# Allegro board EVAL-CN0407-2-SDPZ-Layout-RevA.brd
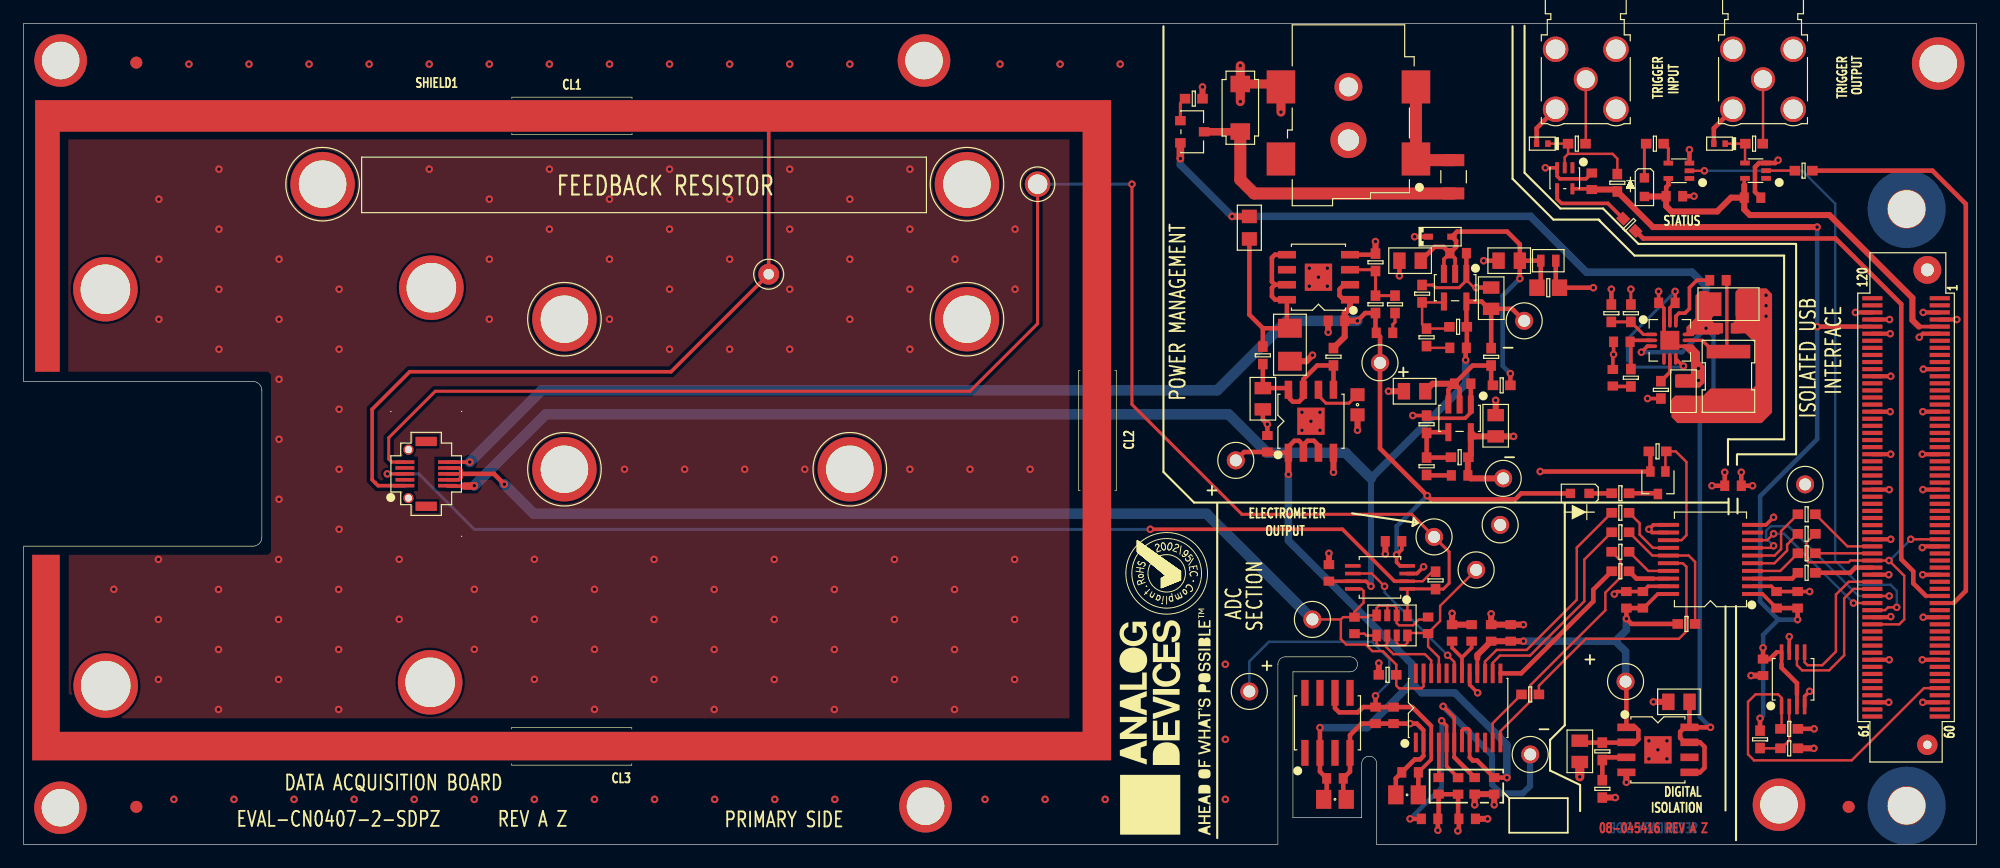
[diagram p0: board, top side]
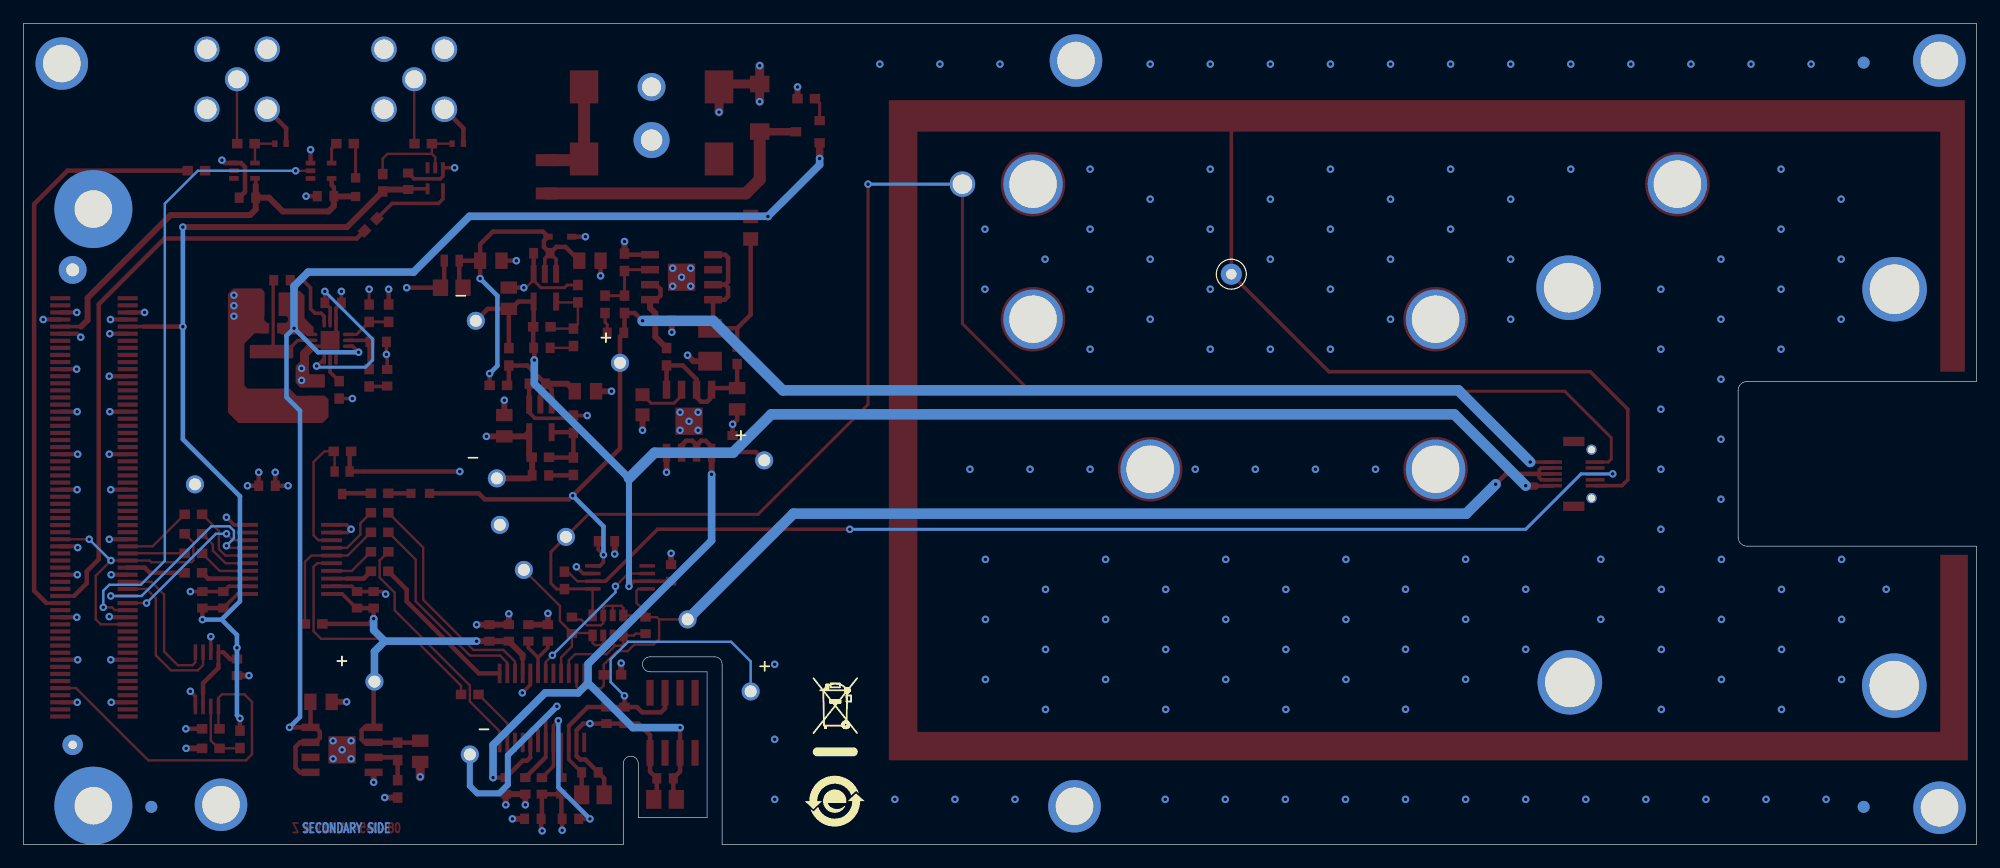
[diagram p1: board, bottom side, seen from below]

Outline 165.1 x 69.47 mm; copper layers: TOP, L2_GND, L3_POWER, BOTTOM. Coordinates in mm from the lower left corner of the outline.
Outline path: 0,39.18 19.38,39.18 arc(19.92,38.96) 20.14,38.42 20.14,26 arc(19.92,25.46) 19.38,25.24 0,25.24 0,0 106.05,0 106.05,15.24 arc(106.23,15.69) 106.68,15.88 112.14,15.88 arc(112.78,15.24) 112.14,14.6 107.32,14.6 107.32,2.26 113.13,2.26 113.14,6.83 arc(113.77,7.46) 114.41,6.83 114.41,0 165.1,0 165.1,69.47 0,69.47 0,39.18

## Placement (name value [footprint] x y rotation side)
AIN0  RED  [CNKEY5001TP]  122.81 23.23 0 top
C1  4.7uF  [C0805#2]  131.58 7.87 90 top
C2  4.7uF  [C0805#2]  139.96 12.06 0 top
C3  10uF  [C1206]  107.06 42.29 90 top
C4  4.7uF  [C0805#2]  104.78 37.72 90 top
C5  10uF  [C0603]  105.16 33.91 270 top
C6  10uF  [C0603]  111 44.31 0 top
C7  10000pF  [C0603]  121.29 42.03 0 top
C8  10uF  [C0603#2]  112.78 37.21 90 top
C9  10000pF  [C0603]  112.52 18.53 270 top
C10  10000pF  [C0603]  115.06 43.3 180 top
C11  0.1uF  [C0603]  121.29 50.04 180 top
C12  0.1uF  [C0603]  121.67 38.99 180 top
C13  4.7uF  [C0805#2]  124.08 46.23 270 top
C14  4.7uF  [C0805#2]  124.46 35.43 270 top
C15  10000pF  [C0603]  121.41 31.23 0 top
C16  4.7uF  [C0805#2]  117.22 49.4 0 top
C17  4.7uF  [C0805#2]  117.61 38.35 0 top
C18  10uF  [C0603]  144.53 30.35 180 top
C23  0.1uF  [C0603]  146.18 54.74 180 top
C24  0.1uF  [C0603]  147.07 14.99 90 top
C25  0.1uF  [C0603]  139.58 54.86 180 top
C26  0.1uF  [C0603]  132.59 56.12 270 top
C27  4.7uF  [C0805#2]  125.61 49.4 0 top
C28  0.1uF  [C0603]  119.64 4.95 90 top
C29  0.1uF  [C0603]  121.29 4.94 90 top
C30  1UF  [C0603]  118.88 2.16 180 top
C31  4.7uF  [C0805]  110.87 3.81 180 top
C32  0.1uF  [C0603]  110.87 5.59 180 top
C33  0.1uF  [C0603]  114.3 10.92 270 top
C34  1UF  [C0603]  115.83 10.92 270 top
C35  4.7uF  [C0805]  116.97 4.19 180 top
C36  0.1uF  [C0603]  117.22 6.1 180 top
C37  0.1uF  [C0603]  124.08 17.9 270 top
C38  1UF  [C0603]  125.73 17.9 270 top
C39  0.1uF  [C0603]  124.34 4.95 90 top
C40  0.1uF  [C0603]  122.43 17.9 270 top
C41  1UF  [C0603]  120.78 17.9 270 top
C42  0.1uF  [C0603]  122.69 4.95 90 top
C43  1UF  [C0603]  122.05 2.16 180 top
C44  0.1uF  [C0603]  149.99 20.7 270 top
C45  0.1uF  [C0603]  115.83 25.65 180 top
C46  0.1uF  [C0603]  110.36 22.98 90 top
C47  10000pF  [C0603]  118.75 18.54 270 top
C48  0.01uF  [C0603]  148.21 20.7 270 top
C49  0.1uF  [C0603]  135.51 20.7 270 top
C50  0.01uF  [C0603]  136.91 20.7 270 top
C51  10pF  [C0603]  135.13 42.54 0 top
C52  4.7uF  [C0805#2]  140.34 38.35 270 top
C53  10uF  [C1206]  144.15 45.72 180 top
C54  1UF  [C0603]  138.94 45.84 0 top
C55  2700PF  [C0603]  134.37 39.5 270 top
C56  1UF  [C0603]  144.02 43.69 180 top
C57  0.01uF  [C0603]  143.26 47.75 180 top
D1  SMAJ15CA-TR  [DO214AC_C]  102.87 62.35 270 top
D2  ESD9M5.0ST5G  [SOD923]  143.39 59.31 180 top
D3  ESD9M5.0ST5G  [SOD923]  128.4 59.31 180 top
D4  RB520S30  [SOD523F]  119.76 51.44 0 top
DS1  LG L29K-G2J1-24-Z  [LED0603-2]  131.57 29.71 180 top
DS2  LG L29K-G2J1-24-Z  [LED0603-2]  137.04 55.63 270 top
E1  600OHM AT 100MEGHZ  [L0805]  103.64 52.2 270 top
F1  0.1A  [F1206H30]  120.9 56.51 270 top
GND_BLK  BLK  [CNKEY5001TP]  124.84 27.04 0 top
GND_BLK2  BLK  [CNKEY5001TP]  150.62 30.47 0 top
J1  PJ-002AH-SMT  [CNCUI-PJ-002A_A]  112.01 61.71 180 top
J2  CONSMA002  [CNSMARAL598W276H401]  147.07 64.76 90 top
J3  CONSMA002  [CNSMARAL598W276H401]  132.08 64.76 90 top
J4  0682-0-15-15-32-27-10-0  [CNTPLD54]  85.73 55.88 0 top
L4  8.2 UH  [LSML193W134H67]  144.15 39.61 270 top
L5  560nH  [L7144]  128.91 49.4 180 top
NOREF  -  [unnamed]  3.11 3.1 0 top
NOREF#2  -  [#2]  58.55 215.51 0 top
NOREF#3  -  [#2]  3.11 3.1 0 top
NOREF#4  -  [#2]  340.95 180.36 0 top
NOREF#5  -  [#2]  107.32 2.26 0 top
NOREF#6  -  [#2]  106.05 0 0 top
NOREF#7  -  [unnamed]  76.25 3.23 0 top
NOREF#8  -  [#2]  165.1 0 0 top
NOREF#9  -  [unnamed]  6.94 13.44 0 top
NOREF#10  -  [#2]  51.69 6.07 0 top
NOREF#11  -  [#2]  -60.07 -138.08 0 top
NOREF#12  -  [unnamed]  79.76 44.45 0 top
NOREF#13  -  [#2]  0 69.47 0 top
NOREF#14  -  [#2]  114.41 0 0 top
NOREF#15  -  [#2]  44.75 4.93 0 top
NOREF#16  -  [#2]  345.19 168.28 0 top
NOREF#17  -  [unnamed]  34.37 13.72 0 top
NOREF#18  -  [#2]  352.68 6.07 0 top
NOREF#19  -  [unnamed]  79.76 55.88 0 top
NOREF#20  -  [#2]  77.85 136.13 0 top
NOREF#21  -  [#2]  3.11 3.1 0 top
NOREF#22  -  [#2]  107.32 14.6 0 top
NOREF#23  -  [#2]  8.51 10.51 0 top
NOREF#24  -  [#2]  100.03 6.05 90 top
NOREF#25  -  [#2]  0 69.47 0 top
NOREF#26  -  [unnamed]  161.88 66.09 0 top
NOREF#27  -  [unnamed]  34.47 47.12 0 top
NOREF#28  -  [#2]  -119.25 215.51 270 top
NOREF#29  -  [#2]  107.32 2.26 0 top
NOREF#30  -  [#2]  213.53 179.06 0 top
NOREF#31  -  [unnamed]  45.72 31.75 0 top
NOREF#32  -  [#2]  343.28 156.9 0 top
NOREF#33  -  [unnamed]  6.91 46.99 0 top
NOREF#34  -  [#2]  0 25.24 0 top
NOREF#35  -  [#2]  -341.5 -235.34 0 top
NOREF#36  -  [#2]  185.55 -89.29 90 top
NOREF#37  -  [#2]  0 0 0 top
NOREF#38  -  [#2]  349.43 180.36 0 top
NOREF#39  -  [#2]  0 0 0 top
NOREF#40  -  [unnamed]  148.42 3.35 0 top
NOREF#41  -  [#2]  -60.07 -138.08 0 top
NOREF#42  -  [#2]  347.09 156.85 0 top
NOREF#43  -  [unnamed]  9.53 3.17 0 top
NOREF#44  -  [#2]  268.1 82.79 0 top
NOREF#45  -  [#2]  185.55 215.51 180 top
NOREF#46  -  [unnamed]  3.13 66.35 0 top
NOREF#47  -  [unnamed]  9.53 66.17 0 top
NOREF#48  -  [#2]  339.52 163.12 0 top
NOREF#49  -  [#2]  104.99 1.24 0 top
NOREF#50  -  [unnamed]  25.28 55.88 0 top
NOREF#51  -  [unnamed]  154.31 3.17 0 top
NOREF#52  -  [#2]  113.14 2.26 0 top
NOREF#53  -  [#2]  20.04 38.8 0 top
NOREF#54  -  [unnamed]  45.72 44.45 0 top
NOREF#55  -  [#2]  -119.25 -89.29 0 top
NOREF#56  -  [#2]  0 39.18 0 top
NOREF#57  -  [#2]  165.1 0 90 top
NOREF#58  -  [unnamed]  69.85 31.75 0 top
NOREF#59  -  [#2]  338.87 171.37 0 top
NOREF#60  -  [unnamed]  76.13 66.34 0 top
NOREF#61  -  [unnamed]  154.31 3.17 180 bottom
NOREF#62  -  [unnamed]  9.53 66.17 180 bottom
NOREF#63  -  [#2]  96.53 3.66 180 bottom
NOREF#64  -  [unnamed]  9.53 3.17 180 bottom
NOREF#65  -  [#2]  96.68 7.52 180 bottom
P6  DF12(3.0)-10DP-0.5V  [CNHRS-DF12_3-10DP-05V]  34.04 31.36 90 top
P7  FX8-120S-SV(21)  [CNHRSFX8-120S-SV_A]  159.16 28.52 270 top
Q1  IRLML5203TRPBF  [SOT23-M3]  98.81 60.32 270 top
Q2  2N7002WT1G  [SOT323]  138.18 30.61 180 top
R1  100K  [R0603]  114.3 45.71 270 top
R2  1K  [R0603]  98.94 63.12 180 top
R3  10K  [R0603]  115.95 45.71 270 top
R4  100K  [R0603]  114.3 49.27 270 top
R5  1K  [R0603]  135 29.72 180 top
R6  100K  [R0603]  121.29 43.81 0 top
R7  10K  [R0603]  135.89 44.96 270 top
R8  100K  [R0603]  121.42 32.77 0 top
R9  32.4K  [R0603]  118.62 42.92 270 top
R10  49.9  [R0603]  135.76 52.44 315 top
R11  91K  [R0603]  118.62 32 270 top
R12  32.4K  [R0603]  118.24 46.61 270 top
R13  91K  [R0603]  118.62 35.56 270 top
R14  0  [R0603]  146.82 8.89 90 top
R15  100K  [R0603]  149.28 9.78 180 top
R16  100K  [R0603]  149.28 8.13 180 top
R17  49.9  [R0603]  146.31 59.31 180 top
R18  1K  [R0603]  137.93 59.31 0 top
R19  49.9  [R0603]  131.32 59.31 180 top
R20  10K  [R0603]  140.59 18.66 180 top
R22  49.9  [R0603]  135 26.42 180 top
R23  49.9  [R0603]  135 23.11 180 top
R24  49.9  [R0603]  135 24.77 180 top
R25  49.9  [R0603]  127.38 12.69 0 top
R26  49.9  [R0603]  135 28.07 0 top
R27  0  [R0603]  110.75 41.28 270 top
R28  0  [R0603]  104.78 41.39 270 top
R29  0  [R0603]  115.32 14.35 0 top
R30  0  [R0603]  124.97 38.85 180 top
R31  0  [R0603]  124.08 41.27 270 top
R32  32.4K  [R0603]  138.15 33.26 0 top
R33  49.9  [R0603]  150.5 57.02 0 top
R34  100K  [R0603]  133.48 4.7 90 top
R35  100K  [R0603]  134.75 56 270 top
R36  0  [R0603]  119.38 22.34 270 top
R37  32.4K  [R0603]  133.48 7.87 90 top
R38  49.9  [R0603]  150.75 27.94 180 top
R39  49.9  [R0603]  150.75 26.29 180 top
R40  49.9  [R0603]  150.75 24.64 180 top
R41  49.9  [R0603]  150.75 22.99 180 top
R43  32.4K  [R0603]  135.89 39.5 90 top
R44  88.7K  [R0603]  138.43 38.47 90 top
R45  86.6K  [R0603]  134.24 44.96 90 top
R46  2.2  [R0805]  128.91 47.12 180 top
REF+  RED  [CNKEY5001TP]  103.63 12.94 0 top
REF-  RED  [CNKEY5001TP]  127.38 7.61 0 top
RN1  10K  [R1206-8P]  115.7 18.53 180 top
SGND  BLK  [CNKEY5001TP]  108.97 19.04 0 top
U1  ADP7118ARDZ-2.5  [SO8NB-PAD2_3X2_3]  138.18 8 270 top
U2  ADP7118ARDZ-2.5  [SO8NB-PAD2_3X2_3]  109.48 48.01 90 top
U3  ADP7118ARDZ-2.5  [SO8NB-PAD2_3X2_3]  108.84 35.81 0 top
U4  ADP7182AUJZ-R7  [TSOT-5]  121.03 47.12 180 top
U5  ADP7182AUJZ-R7  [TSOT-5]  121.41 36.06 180 top
U8  24LC32A-I/MS  [MSOP8]  149.61 13.97 0 top
U9  SN74AHCT1G04DCKR  [SC70-5]  146.43 57.02 90 top
U10  SN74AHCT1G04DCKR  [SC70-5]  139.95 57.01 90 top
U11  74LVC1G14GW,125  [SOT353]  130.3 56.38 180 top
U12  ADR4525BRZ  [SO8]  110.24 10.29 0 top
U13  AD7172-2BRUZ  [TSSOP24]  121.29 11.55 0 top
U14  ADG1419BRMZ  [MSOP8]  114.68 22.6 90 top
U15  ADUM3151BRSZ  [SSOP20-4]  142.62 24.12 90 top
U17  ADP2442ACPZ  [QFN12_3X3_PAD1_6X1_6]  139.19 42.66 270 top
UNK+2.5VA  RED  [CNKEY5001TP]  102.49 32.5 0 top
UNK+3.3VISO  RED  [CNKEY5001TP]  135.44 13.78 0 top
UNK+5VA  RED  [CNKEY5001TP]  114.68 40.76 0 top
UNK-2.5VA  RED  [CNKEY5001TP]  125.09 30.98 0 top
UNK-5VA  RED  [CNKEY5001TP]  126.87 44.31 0 top
VGUARD  TP_VIA_LARGE  [TPC70D35]  63 48.26 0 top
VOUT  RED  [CNKEY5001TP]  119.25 26.03 0 top

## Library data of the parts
AIN0 REF+ REF- UNK+2.5VA UNK+3.3VISO UNK+5VA UNK-2.5VA UNK-5VA VOUT = CNTP1P: Tolerance: N/A; User Part Number: UPN; alternate symbols: (); part number: CNTP1P_TH-RED,E016323,CNKEY5001TP; tolerance: N/A
C1 C2 C4 C13 C14 C16 C17 C27 C52 = CAP: Tolerance: 10; User Part Number: UPN; alternate symbols: C0805H30; part number: CAP_SM-4.7UF,16V,10,E011042,C0805; tolerance: 10
C3 C53 = CAP: Tolerance: 10; User Part Number: UPN; alternate symbols: C1206H37; part number: CAP_SM-10UF,10V,10,E011047,C1206; tolerance: 10
C5 C6 C8 C18 = CAP: Tolerance: 20; User Part Number: UPN; alternate symbols: C0603L_ALT; part number: CAP_SM-10UF,6.3V,20,E007143,C0603; tolerance: 20
C7 C9 C10 C15 C47 = CAP: Tolerance: 10; User Part Number: UPN; alternate symbols: C0603L_ALT; part number: CAP_SM-10000PF,25V,10,E014286,C0603; tolerance: 10
C11 C12 C23-C26 C28 C29 C32 C33 C36 C37 C39 C40 C42 C44-C46 C49 = CAP: Tolerance: 10; User Part Number: UPN; alternate symbols: C0603L_ALT; part number: CAP_SM-0.1UF,25V,10,E013746,C0603; tolerance: 10
C30 C34 C38 C41 C43 C54 C56 = CAP: Tolerance: 10; User Part Number: UPN; alternate symbols: C0603L_ALT; part number: CAP_SM-1UF,25V,10,E025743,C0603; tolerance: 10
C31 C35 = CAP: Tolerance: 10; User Part Number: UPN; alternate symbols: (); part number: CAP_SM-4.7UF,16V,10,E011042,C0805; tolerance: 10
C48 C50 C57 = CAP: Tolerance: 10; User Part Number: UPN; alternate symbols: C0603L_ALT; part number: CAP_SM-0.01UF,50V,10,E017640,C0603; tolerance: 10
C51 = CAP: Tolerance: 5; User Part Number: UPN; alternate symbols: C0603L_ALT; part number: CAP_SM-10PF,50V,5,E010138,C0603; tolerance: 5
C55 = CAP: Tolerance: 5; User Part Number: UPN; alternate symbols: C0603L_ALT; part number: CAP_SM-2700PF,50V,5,E026401,C0603; tolerance: 5
D1 = DIO_V3: User Part Number: UPN; Tolerance: N/A; alternate symbols: (); part number: DIO_V3_SM-SMAJ15CA-TR,15V,N/A,E027980,DO214AC_C; tolerance: N/A
D2 D3 = DIOZNR: User Part Number: UPN; Tolerance: N/A; alternate symbols: (); part number: DIOZNR_SM-ESD9M5.0ST5G,5V,N/A,E027990,SOD923; tolerance: N/A
D4 = DIOSCHOTTKY: Tolerance: N/A; User Part Number: UPN; alternate symbols: (); part number: DIOSCHOTTKY_SM-RB520S30,30V,N/A,E012252,SOD523F; tolerance: N/A
DS1 DS2 = DIOLED: Tolerance: N/A; User Part Number: UPN; alternate symbols: (); part number: DIOLED_SM-LG L29K-G2J1-24-Z,N/A,N/A,E010948,LED0603-2; tolerance: N/A
E1 = FERRITE: Tolerance: 25; User Part Number: UPN; alternate symbols: (); part number: FERRITE_SM-600OHM AT 100MEGHZ,25,E020490,L0805; tolerance: 25
F1 = FSFUSE: Tolerance: N/A; User Part Number: UPN; alternate symbols: (); part number: FSFUSE_SM-0.1A,60V,E027979,F1206H30; tolerance: N/A
GND_BLK GND_BLK2 SGND = CNTP1P: Tolerance: N/A; User Part Number: UPN; alternate symbols: (); part number: CNTP1P_TH-BLK,E005347,CNKEY5001TP; tolerance: N/A
J1 = CN4P_V6: User Part Number: UPN; Tolerance: N/A; alternate symbols: (); part number: CN4P_V6_SM-PJ-002AH-SMT,E022246,CNCUI-PJ-002A_A; tolerance: N/A
J2 J3 = CNBNC5P: User Part Number: UPN; Tolerance: N/A; alternate symbols: (); part number: CNBNC5P_TH-CONSMA002,E028005,CNSMARAL598W276H401; tolerance: N/A
J4 = CNTP1P: Tolerance: N/A; User Part Number: UPN; alternate symbols: (); part number: CNTP1P_TH-0682-0-15-15-32-27-10-0,E014020,CNTPLD54; tolerance: N/A
L4 = IND: User Part Number: UPN; Tolerance: 20; alternate symbols: (); part number: IND_SM-8.2 UH,20,E027982,LSML193W134H67; tolerance: 20
L5 = IND: Tolerance: 20; User Part Number: UPN; alternate symbols: (); part number: IND_SM-560NH,20,E021672,L7144; tolerance: 20
P6 = CN10P_ODD_EVEN: User Part Number: UPN; Tolerance: N/A; alternate symbols: (); part number: CN10P_ODD_EVEN_SM-DF12(3.0)-10DP-0.5V,E017886,CNHRS-DF12_3-10DP-05V; tolerance: N/A
P7 = CN120P_V4: User Part Number: UPN; Tolerance: N/A; alternate symbols: (); part number: CN120P_V4_SM-FX8-120S-SV(21),E016993,CNHRSFX8-120S-SV_A; tolerance: N/A
Q1 = TRANPMOSFET_V12: User Part Number: UPN; Tolerance: N/A; alternate symbols: (); part number: TRANPMOSFET_V12_SM-IRLML5203TRPBF,E027978,SOT23-M3; tolerance: N/A
Q2 = TRANNMOSFET3P: User Part Number: UPN; Tolerance: N/A; alternate symbols: (); part number: TRANNMOSFET3P_SM-2N7002WT1G,E020753,SOT323; tolerance: N/A
R1 R4 R6 R8 R15 R16 R34 R35 = RES: Tolerance: 0.5; User Part Number: UPN; alternate symbols: R0603_A; part number: RES_SM-100K,E012705,1/10W,0.5,R0603; tolerance: 0.5
R2 R5 R18 = RES: Tolerance: 1; User Part Number: UPN; alternate symbols: R0603_A; part number: RES_SM-1K,E003678,1/10W,1,R0603; tolerance: 1
R3 R7 R20 = RES: Tolerance: 0.1; User Part Number: UPN; alternate symbols: R0603_A; part number: RES_SM-10K,E020748,1/10W,0.1,R0603; tolerance: 0.1
R9 R12 R32 R37 R43 = RES: Tolerance: 0.5; User Part Number: UPN; alternate symbols: R0603_A; part number: RES_SM-32.4K,E027989,1/10W,0.5,R0603; tolerance: 0.5
R10 R17 R19 R22-R26 R33 R38-R41 = RES: Tolerance: 1; User Part Number: UPN; alternate symbols: R0603_A; part number: RES_SM-49.9,E003673,1/10W,1,R0603; tolerance: 1
R11 R13 = RES: Tolerance: 1; User Part Number: UPN; alternate symbols: R0603_A; part number: RES_SM-91K,E022344,1/10W,1,R0603; tolerance: 1
R14 R27-R31 R36 = RES: Tolerance: 1; User Part Number: UPN; alternate symbols: R0603_A; part number: RES_SM-0,E004207,1/16W,1,R0603; tolerance: 1
R44 = RES: Tolerance: 1; User Part Number: UPN; alternate symbols: R0603_A; part number: RES_SM-88.7K,E027521,1/10W,1,R0603; tolerance: 1
R45 = RES: Tolerance: 1; User Part Number: UPN; alternate symbols: R0603_A; part number: RES_SM-86.6K,E027997,1/10W,1,R0603; tolerance: 1
R46 = RES: Tolerance: 1; User Part Number: UPN; alternate symbols: R0603_A; part number: RES_SM-2.2,E023444,1/3W,1,R0805; tolerance: 1
RN1 = RESNET_8P_4R: Tolerance: 0.1; User Part Number: UPN; alternate symbols: (); part number: RESNET_8P_4R_SM-10K,E027995,3/10W,0.1,R1206-8P; tolerance: 0.1
U1-U3 = ADP7118_V3: Tolerance: N/A; User Part Number: UPN; alternate symbols: (); part number: ADP7118_V3_SM-ADP7118ARDZ-2.5,E023599,SO8NB-PAD2_3X2_3; tolerance: N/A
U4 U5 = ADP7182: User Part Number: UPN; Tolerance: N/A; alternate symbols: (); part number: ADP7182_SM-ADP7182AUJZ-R7,E017566,TSOT-5; tolerance: N/A
U8 = IC24FC256: Tolerance: N/A; User Part Number: UPN; alternate symbols: (); part number: IC24FC256_SM-24LC32A-I/MS,E014160,MSOP8; tolerance: N/A
U9 U10 = 741G04: Tolerance: N/A; User Part Number: UPN; alternate symbols: (); part number: 741G04_SM-SN74AHCT1G04DCKR,E027985,SC70-5; tolerance: N/A
U11 = 741G14: User Part Number: UPN; Tolerance: N/A; alternate symbols: (); part number: 741G14_SM-74LVC1G14GW,125,E027983,SOT353; tolerance: N/A
U12 = ADR45XX: Tolerance: N/A; User Part Number: UPN; alternate symbols: (); part number: ADR45XX_SM-ADR4525BRZ,E016680,SO8; tolerance: N/A
U13 = AD7172_2: Tolerance: N/A; User Part Number: UPN; alternate symbols: (); part number: AD7172_2_SM-AD7172-2BRUZ,E026892,TSSOP24; tolerance: N/A
U14 = ADG1419: Tolerance: N/A; User Part Number: UPN; alternate symbols: (); part number: ADG1419_SM-ADG1419BRMZ,E014853,MSOP8; tolerance: N/A
U15 = ADUM3151: Tolerance: N/A; User Part Number: UPN; alternate symbols: (); part number: ADUM3151_SM-ADUM3151BRSZ,E021805,SSOP20-4; tolerance: N/A
U17 = ADP2442: User Part Number: UPN; Tolerance: N/A; alternate symbols: (); part number: ADP2442_SM-ADP2442ACPZ,E018413,QFN12_3X3_PAD1_6X1_6; tolerance: N/A
VGUARD = NCTESTPAD: Tolerance: N/A; User Part Number: UPN; alternate symbols: (); part number: NCTESTPAD_TH-TP_VIA_LARGE,E012150,TPC70D35; tolerance: N/A

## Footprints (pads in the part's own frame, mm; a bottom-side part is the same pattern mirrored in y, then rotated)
C0603
  rect 0.762x0.889 smd: 1(-0.699,0) 2(0.699,0)
C0603#2
  rect 1.092x1.194 smd: 1(-0.851,0) 2(0.851,0)
C0805
  rect 1.295x1.6 smd: 1(-0.953,0) 2(0.953,0)
C0805#2
  rect 1.041x1.397 smd: 1(-0.9,0) 2(0.9,0)
C1206
  rect 1.6x2.007 smd: 1(-1.397,0) 2(1.397,0)
CNCUI-PJ-002A_A
  round 3.048 hole 1.803 unplated: (0,2.1)
  round 2.362 hole 1.6 unplated: (0,-2.4)
  rect 2.413x2.794 smd: 1A(-5.707,3.7) 1B(-5.707,-2.4) 2(5.707,-2.4) 3(5.707,3.7)
CNHRS-DF12_3-10DP-05V
  rect 0.787x1.803 smd: (-2.744,0) (2.744,0)
  round 0.864 hole 0.61 unplated: (-2.05,1.5) (2.05,1.5)
  rect 0.305x1.6 smd: 1(-1,1.8) 2(-1,-1.8) 3(-0.5,1.8) 4(-0.5,-1.8) 5(0,1.8) 6(0,-1.8) 7(0.5,1.8) 8(0.5,-1.8) 9(1,1.8) 10(1,-1.8)
CNHRSFX8-120S-SV_A
  round 3.302 hole 3.175 unplated: (-25.25,0.05) (25.25,0.05)
  round 2.362 hole 1.092 unplated: (-20.1,1.8)
  round 1.727 hole 0.711 unplated: (20.1,1.8)
  rect 0.356x1.702 smd: 1(-17.7,2.851) 2(-17.1,2.851) 3(-16.5,2.851) 4(-15.9,2.851) 5(-15.3,2.851) 6(-14.7,2.851) 7(-14.1,2.851) 8(-13.5,2.851) 9(-12.9,2.851) 10(-12.3,2.851) 11(-11.7,2.851) 12(-11.1,2.851) 13(-10.5,2.851) 14(-9.9,2.851) 15(-9.3,2.851) 16(-8.7,2.851) 17(-8.1,2.851) 18(-7.5,2.851) 19(-6.9,2.851) 20(-6.3,2.851) 21(-5.7,2.851) 22(-5.1,2.851) 23(-4.5,2.851) 24(-3.9,2.851) 25(-3.3,2.851) 26(-2.7,2.851) 27(-2.1,2.851) 28(-1.5,2.851) 29(-0.9,2.851) 30(-0.3,2.851) 31(0.3,2.851) 32(0.9,2.851) 33(1.5,2.851) 34(2.1,2.851) 35(2.7,2.851) 36(3.3,2.851) 37(3.9,2.851) 38(4.5,2.851) 39(5.1,2.851) 40(5.7,2.851) 41(6.3,2.851) 42(6.9,2.851) 43(7.5,2.851) 44(8.1,2.851) 45(8.7,2.851) 46(9.3,2.851) 47(9.9,2.851) 48(10.5,2.851) 49(11.1,2.851) 50(11.7,2.851) 51(12.3,2.851) 52(12.9,2.851) 53(13.5,2.851) 54(14.1,2.851) 55(14.7,2.851) 56(15.3,2.851) 57(15.9,2.851) 58(16.5,2.851) 59(17.1,2.851) 60(17.7,2.851) 61(17.7,-2.851) 62(17.1,-2.851) 63(16.5,-2.851) 64(15.9,-2.851) 65(15.3,-2.851) 66(14.7,-2.851) 67(14.1,-2.851) 68(13.5,-2.851) 69(12.9,-2.851) 70(12.3,-2.851) 71(11.7,-2.851) 72(11.1,-2.851) 73(10.5,-2.851) 74(9.9,-2.851) 75(9.3,-2.851) 76(8.7,-2.851) 77(8.1,-2.851) 78(7.5,-2.851) 79(6.9,-2.851) 80(6.3,-2.851) 81(5.7,-2.851) 82(5.1,-2.851) 83(4.5,-2.851) 84(3.9,-2.851) 85(3.3,-2.851) 86(2.7,-2.851) 87(2.1,-2.851) 88(1.5,-2.851) 89(0.9,-2.851) 90(0.3,-2.851) 91(-0.3,-2.851) 92(-0.9,-2.851) 93(-1.5,-2.851) 94(-2.1,-2.851) 95(-2.7,-2.851) 96(-3.3,-2.851) 97(-3.9,-2.851) 98(-4.5,-2.851) 99(-5.1,-2.851) 100(-5.7,-2.851) 101(-6.3,-2.851) 102(-6.9,-2.851) 103(-7.5,-2.851) 104(-8.1,-2.851) 105(-8.7,-2.851) 106(-9.3,-2.851) 107(-9.9,-2.851) 108(-10.5,-2.851) 109(-11.1,-2.851) 110(-11.7,-2.851) 111(-12.3,-2.851) 112(-12.9,-2.851) 113(-13.5,-2.851) 114(-14.1,-2.851) 115(-14.7,-2.851) 116(-15.3,-2.851) 117(-15.9,-2.851) 118(-16.5,-2.851) 119(-17.1,-2.851) 120(-17.7,-2.851)
CNKEY5001TP
  round 1.524 hole 1.016: 1(0,0)
CNSMARAL598W276H401
  round 2.032 hole 1.524: 1(0,0)
  round 2.159 hole 1.651: 2(2.54,-2.553) 3(2.54,2.553) 4(-2.54,2.553) 5(-2.54,-2.553)
CNTPLD54
  round 2.159 hole 1.651: 1(0,0)
DO214AC_C
  rect 1.397x1.651 smd: 1(-2.014,0) 2(2.014,0)
F1206H30
  rect 1.016x1.803 smd: 1(-1.41,0) 2(1.41,0)
L0805
  rect 1.143x1.27 smd: 1(-0.953,0) 2(0.953,0)
L7144
  rect 0.635x1.016 smd: 1(-0.635,0) 2(0.635,0)
LED0603-2
  rect 0.787x0.787 smd: A(0.787,0) C(-0.787,0)
LSML193W134H67
  rect 1.143x3.683 smd: 1(-2.095,0) 2(2.095,0)
MSOP8
  rect 0.305x1.321 smd: 1(-0.975,-2.3) 2(-0.325,-2.3) 3(0.325,-2.3) 4(0.975,-2.3) 5(0.975,2.3) 6(0.325,2.3) 7(-0.325,2.3) 8(-0.975,2.3)
QFN12_3X3_PAD1_6X1_6
  oval 0.305x0.991 smd: 1(-0.5,-1.57) 2(0,-1.57) 3(0.5,-1.57) 7(0.5,1.57) 8(0,1.57) 9(-0.5,1.57)
  oval 0.991x0.305 smd: 4(1.57,-0.5) 5(1.57,0) 6(1.57,0.5) 10(-1.57,0.5) 11(-1.57,0) 12(-1.57,-0.5)
  rect 1.6x1.6 smd: PAD(0,0)
R0603
  rect 0.889x0.813 smd: 1(-0.737,0) 2(0.737,0)
R0805
  rect 1.295x1.397 smd: 1(-0.953,0) 2(0.953,0)
R1206-8P
  rect 0.711x0.991 smd: 1(-1.302,-0.85) 4(1.302,-0.85) 5(1.302,0.85) 8(-1.302,0.85)
  rect 0.508x0.991 smd: 2(-0.4,-0.85) 3(0.4,-0.85) 6(0.4,0.85) 7(-0.4,0.85)
SC70-5
  rect 0.406x0.813 smd: 1(-0.65,-0.89) 2(0,-0.89) 3(0.65,-0.89) 4(0.65,0.89) 5(-0.65,0.89)
SO8
  rect 0.61x2.184 smd: 1(-1.905,-2.54) 2(-0.635,-2.54) 3(0.635,-2.54) 4(1.905,-2.54) 5(1.905,2.54) 6(0.635,2.54) 7(-0.635,2.54) 8(-1.905,2.54)
SO8NB-PAD2_3X2_3
  rect 0.635x1.524 smd: 1(-1.905,-2.667) 2(-0.635,-2.667) 3(0.635,-2.667) 4(1.905,-2.667) 5(1.905,2.667) 6(0.635,2.667) 7(-0.635,2.667) 8(-1.905,2.667)
  rect 2.311x2.311 smd: PAD(0,0)
SOD523F
  rect 0.787x0.508 smd: A(1,0) C(-1,0)
SOD923
  rect 0.457x0.559 smd: A(0.479,0) C(-0.479,0)
SOT23-M3
  rect 0.787x0.889 smd: 1(-0.94,-1.003) 2(0.94,-1.003) 3(0,1.003)
SOT323
  rect 0.711x0.889 smd: 1(-0.635,-0.953) 2(0.635,-0.953) 3(0,0.953)
SOT353
  rect 0.33x0.94 smd: 1(-0.65,-0.89) 2(0,-0.89) 3(0.65,-0.89) 4(0.65,0.89) 5(-0.65,0.89)
SSOP20-4
  rect 0.33x1.778 smd: 1(-2.925,-3.555) 2(-2.275,-3.555) 3(-1.625,-3.555) 4(-0.975,-3.555) 5(-0.325,-3.555) 6(0.325,-3.555) 7(0.975,-3.555) 8(1.625,-3.555) 9(2.275,-3.555) 10(2.925,-3.555) 11(2.925,3.555) 12(2.275,3.555) 13(1.625,3.555) 14(0.975,3.555) 15(0.325,3.555) 16(-0.325,3.555) 17(-0.975,3.555) 18(-1.625,3.555) 19(-2.275,3.555) 20(-2.925,3.555)
TPC70D35
  round 1.778 hole 0.889: 1(0,0)
TSOT-5
  rect 0.508x1.524 smd: 1(-0.95,-1.17) 2(0,-1.17) 3(0.95,-1.17) 4(0.95,1.17) 5(-0.95,1.17)
TSSOP24
  rect 0.33x1.651 smd: 1(-3.575,-2.92) 2(-2.925,-2.92) 3(-2.275,-2.92) 4(-1.625,-2.92) 5(-0.975,-2.92) 6(-0.325,-2.92) 7(0.325,-2.92) 8(0.975,-2.925) 9(1.625,-2.925) 10(2.275,-2.925) 11(2.925,-2.925) 12(3.575,-2.925) 13(3.575,2.925) 14(2.925,2.925) 15(2.275,2.925) 16(1.625,2.93) 17(0.975,2.93) 18(0.325,2.93) 19(-0.325,2.93) 20(-0.975,2.93) 21(-1.625,2.93) 22(-2.275,2.93) 23(-2.925,2.93) 24(-3.575,2.93)
unnamed
  round 4.445 hole 3.175 unplated: (0,0)

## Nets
+2.5VA: C5.2(N2) C31.2(N2) C32.2(N2) C39.2(N2) U3.1(VOUT1) U3.2(VOUT2) U3.3(SENSE/ADJ) U12.2(VIN) U13.7(AVDD1) U13.8(AVDD2) UNK+2.5VA.1
+3.3VIO: C24.2(N2) C26.2(N2) C44.2(N2) C48.2(N2) P7.116(VIO(+3.3V)) R14.2(N2) R35.2(N2) U8.3(A2) U8.8(VCC) U11.5(VCC) U15.1(VDD1)
+3.3VISO: C1.2(N2) C37.2(N2) C38.2(N2) C49.2(N2) C50.2(N2) R20.2(N2) R37.2(N2) U1.1(VOUT1) U1.2(VOUT2) U13.16(IOVDD) U15.20(VDD2) UNK+3.3VISO.1
+5V_USB: C23.2(N2) C25.2(N2) DS2.A(P) P7.5(USB_VBUS) U9.5(VCC) U10.5(VCC)
+5VA: C6.2(N2) C10.2(N2) C45.1(N1) DS1.A(P) P6.10(N5) R1.2(N2) R27.1(N1) U2.1(VOUT1) U2.2(VOUT2) U14.4(VDD) UNK+5VA.1
+VIN_PROTECTED: C2.2(N2) C53.2(N2) C56.2(N2) E1.1(N1) Q1.2(S) U1.5(EN) U1.7(VIN1) U1.8(VIN2) U17.3(EN) U17.9(VIN)
-2.5VA: C14.2(N2) C15.2(N2) C28.1(N1) C29.1(N1) C30.1(N1) C31.1(N1) C32.1(N1) C33.2(N2) C34.2(N2) C35.2(N2) C36.2(N2) C42.2(N2) C43.2(N2) R8.2(N2) REF-.1(N1) U5.5(VOUT) U12.4(GND) U13.2(REF-) U13.6(AVSS) U14.3(GND) UNK-2.5VA.1
-5.8V_RAW: C51.1(N1) C52.1(N1) C54.1(N1) C55.1(N1) L5.1(N1) R7.1(N1) R44.1(N1) R46.1(N1) U17.7(PGND) U17.12(AGND) U17.PAD
-5VA: C7.2(N2) C13.2(N2) C46.1(N1) P6.2(N1) R6.2(N2) R31.1(N1) U4.5(VOUT) U14.7(VSS) UNK-5VA.1
AGND: C1.1(N1) C2.1(N1) C3.1(N1) C4.1(N1) C5.1(N1) C6.1(N1) C8.1(N1) C11.1(N1) C12.1(N1) C13.1(N1) C14.1(N1) C16.1(N1) C17.1(N1) C18.2(N2) C27.1(N1) C37.1(N1) C38.1(N1) C39.1(N1) C40.1(N1) C41.1(N1) C42.1(N1) C43.1(N1) C45.2(N2) C46.2(N2) C49.1(N1) C50.1(N1) C52.2(N2) C53.1(N1) C56.1(N1) D1.1(N1) D4.C(N) GND_BLK.1(N1) J1.2(N3) L4.2(N2) Q2.2(S) R2.1(N1) R4.1(N1) R12.1(N1) R13.1(N1) R29.1(N1) R32.1(N1) R34.1(N1) R45.2(N2) U1.4(GND) U1.PAD U2.4(GND) U2.PAD U3.4(GND) U3.PAD U4.1(GND) U5.1(GND) U13.17(DGND) U15.11(GND2_1) U15.12(VIC) U15.19(GND2_2)
AGND2: C18.1(N1) C23.1(N1) C24.1(N1) C25.1(N1) C26.1(N1) C44.1(N1) C48.1(N1) D2.A(P) D3.A(P) GND_BLK2.1(N1) J2.2(SH1) J2.3(SH2) J2.4(SH3) J2.5(SH4) J3.2(SH1) J3.3(SH2) J3.4(SH3) J3.5(SH4) P7.3(GND1) P7.4(GND2) P7.6(GND3) P7.11(GND4) P7.17(GND5) P7.23(GND6) P7.28(GND7) P7.36(GND8) P7.40(GND9) P7.46(GND10) P7.52(GND11) P7.58(GND12) P7.63(GND13) P7.69(GND14) P7.75(GND15) P7.81(GND16) P7.86(GND17) P7.93(GND18) P7.98(GND19) P7.104(GND20) P7.109(GND21) P7.115(GND22) P7.117(GND23) P7.118(GND24) R15.1(N1) R16.1(N1) U8.4(VSS) U8.7(WP) U9.3(GND) U10.3(GND) U11.3(GND) U15.2(GND1_1) U15.10(GND1_2)
CS: R20.1(N1) R22.1(N1) U15.15(SSS_N)
DIN: R24.1(N1) U15.17(SI)
DOUT: R25.2(N2) U15.16(SO)
EN_ADCOFFSETCAL: U13.19(GPIO0) U14.6(IN)
GP_LED_ON: P7.76(GPIO5) U10.2(A)
LED_ONI: Q2.1(G) R32.2(N2) U15.13(VOB)
SCLK: R23.1(N1) U15.18(SCLK)
SPI_MISO_SDP: P7.35(SERIAL_INT) P7.74(GPIO7) P7.83(SPI_MISO) R39.1(N1)
START_TRIGGER_OUT: R33.1(N1) U9.2(A)
SYNCI: R26.2(N2) U15.14(VOA)
TRIGGER_INPUT: P7.43(GPIO0) R10.2(N2)
UNNAMED_3_ADP2442_I8_BST: C57.2(N2) U17.10(BST)
UNNAMED_3_ADP2442_I8_COMP: C51.2(N2) R43.2(N2) U17.2(COMP)
UNNAMED_3_ADP2442_I8_FB: R7.2(N2) R45.1(N1) U17.1(FB)
UNNAMED_3_ADP2442_I8_FREQ: R44.2(N2) U17.5(FREQ)
UNNAMED_3_ADP2442_I8_SW: C57.1(N1) L4.1(N1) U17.8(SW)
UNNAMED_3_ADP2442_I8_SYNC: C54.2(N2) U17.6(SYNC/MODE) U17.11(VCC)
UNNAMED_3_ADP7118V3_I3_EN: C4.2(N2) R27.2(N2) R28.2(N2) U3.5(EN) U3.7(VIN1) U3.8(VIN2)
UNNAMED_3_ADP7118V3_I3_SS: C8.2(N2) U3.6(SS)
UNNAMED_3_ADP7118V3_I4_EN: C3.2(N2) E1.2(N2) R28.1(N1) U2.5(EN) U2.7(VIN1) U2.8(VIN2)
UNNAMED_3_ADP7118V3_I4_SENSE: R1.1(N1) R3.1(N1) R4.2(N2) U2.3(SENSE/ADJ)
UNNAMED_3_ADP7118V3_I5_SENSE: R34.2(N2) R37.1(N1) U1.3(SENSE/ADJ)
UNNAMED_3_ADP7182_I6_ADJ: R6.1(N1) R9.1(N1) R12.2(N2) U4.4(ADJ)
UNNAMED_3_ADP7182_I6_EN: C11.2(N2) C16.2(N2) C27.2(N2) D4.A(P) L5.2(N2) R30.1(N1) R46.2(N2) U4.2(VIN) U4.3(EN)
UNNAMED_3_ADP7182_I7_ADJ: R8.1(N1) R11.1(N1) R13.2(N2) U5.4(ADJ)
UNNAMED_3_ADP7182_I7_EN: C12.2(N2) C17.2(N2) R30.2(N2) R31.2(N2) U5.2(VIN) U5.3(EN)
UNNAMED_3_CAP_I33_N1: C10.1(N1) R3.2(N2)
UNNAMED_3_CAP_I56_N1: C15.1(N1) R11.2(N2)
UNNAMED_3_CAP_I57_N1: C7.1(N1) R9.2(N2)
UNNAMED_3_CAP_I91_N2: C55.2(N2) R43.1(N1)
UNNAMED_3_CN4PV6_I1_N1: F1.1(N1) J1.1A(N1) J1.1B(N2)
UNNAMED_3_DIOLED_I44_N: DS1.C(N) R5.2(N2)
UNNAMED_3_DIOV3_I120_N2: D1.2(N2) F1.2(N2) Q1.3(D)
UNNAMED_3_RES_I16_N2: Q1.1(G) R2.2(N2)
UNNAMED_3_RES_I43_N1: Q2.3(D) R5.1(N1)
UNNAMED_4_AD71722_I1_AIN0: AIN0.1(N1) C47.2(N2) RN1.7(N2) RN1.8(N2) U13.21(AIN0)
UNNAMED_4_AD71722_I1_AIN1: C9.2(N2) RN1.5(N2) RN1.6(N2) U13.22(AIN1)
UNNAMED_4_AD71722_I1_AIN2: C9.1(N1) C47.1(N1) P6.4(N2) P6.6(N3) P6.8(N4) R29.2(N2) RN1.2(N1) RN1.3(N1) RN1.4(N1) SGND.1(N1) U13.23(AIN2) U14.8(SB)
UNNAMED_4_AD71722_I1_CSN: R22.2(N2) U13.14(CS_N)
UNNAMED_4_AD71722_I1_DIN: R24.2(N2) U13.12(DIN)
UNNAMED_4_AD71722_I1_DOUT: R25.1(N1) U13.11(DOUT/RDY_N)
UNNAMED_4_AD71722_I1_REF: C33.1(N1) C34.1(N1) C35.1(N1) C36.1(N1) REF+.1(N1) U12.6(VOUT) U13.3(REF+)
UNNAMED_4_AD71722_I1_REFOUT: C28.2(N2) U13.4(REFOUT)
UNNAMED_4_AD71722_I1_SCLK: R23.2(N2) U13.13(SCLK)
UNNAMED_4_AD71722_I1_SYNCN: R26.1(N1) U13.15(SYNC_N/ERROR_N)
UNNAMED_4_ADG1419_I8_D: J4.1(N1) P6.9(N5) R36.2(N2) RN1.1(N1) U14.1(D) VOUT.1(N1)
UNNAMED_4_ADG1419_I8_SA: P6.5(N3) R36.1(N1) U14.2(SA)
UNNAMED_4_CAP_I35_N2: C29.2(N2) C30.2(N2) U13.5(REGCAPA)
UNNAMED_4_CAP_I42_N2: C40.2(N2) C41.2(N2) U13.18(REGCAPD)
UNNAMED_5_741G04_I48_Y: D2.C(N) R17.2(N2) U9.4(Y)
UNNAMED_5_741G04_I49_Y: R18.2(N2) U10.4(Y)
UNNAMED_5_741G14_I52_Y: R10.1(N1) U11.4(Y)
UNNAMED_5_ADUM3151_I16_MCLK: R41.2(N2) U15.3(MCLK)
UNNAMED_5_ADUM3151_I16_MI: R39.2(N2) U15.5(MI)
UNNAMED_5_ADUM3151_I16_MO: R40.2(N2) U15.4(MO)
UNNAMED_5_ADUM3151_I16_MSSN: R38.2(N2) U15.6(MSS_N)
UNNAMED_5_ADUM3151_I16_VIA: P7.78(GPIO1) U15.7(VIA)
UNNAMED_5_ADUM3151_I16_VIB: P7.77(GPIO3) U15.8(VIB)
UNNAMED_5_CN120PV4_I1_EEPROMA0: P7.56(EEPROM_A0) R15.2(N2) U8.1(A0)
UNNAMED_5_CN120PV4_I1_GPIO2: P7.44(GPIO2) R33.2(N2)
UNNAMED_5_CN120PV4_I1_SCL0: P7.79(SCL_0) U8.6(SCL)
UNNAMED_5_CN120PV4_I1_SDA0: P7.80(SDA_0) U8.5(SDA)
UNNAMED_5_CN120PV4_I1_SPICLK: P7.82(SPI_CLK) R41.1(N1)
UNNAMED_5_CN120PV4_I1_SPIMOSI: P7.84(SPI_MOSI) R40.1(N1)
UNNAMED_5_CN120PV4_I1_SPISELA: P7.85(SPI_SEL_A) R38.1(N1)
UNNAMED_5_CNBNC5P_I53_CNTR: J2.1(CNTR) R17.1(N1)
UNNAMED_5_CNBNC5P_I54_CNTR: J3.1(CNTR) R19.1(N1)
UNNAMED_5_DIOLED_I62_N: DS2.C(N) R18.1(N1)
UNNAMED_5_IC24FC256_I3_A1: R14.1(N1) R16.2(N2) U8.2(A1)
UNNAMED_5_RES_I26_N1: D3.C(N) R19.2(N2) R35.1(N1) U11.2(A)
VGUARD: P6.1(N1) VGUARD.1(N1)

Pads without a net: J1 3; P6 3 7; P7 1 2 7 8 9 10 12 13 14 15 16 18 19 20 21 22 24 25 26 27 29 30 31 32 33 34 37 38 39 41 42 45 47 48 49 50 51 53 54 55 57 59 60 61 62 64 65 66 67 68 70 71 72 73 87 88 89 90 91 92 94 95 96 97 99 100 101 102 103 105 106 107 108 110 111 112 113 114 119 120; U1 6; U2 6; U9 1; U10 1; U11 1; U12 1 3 5 7 8; U13 1 9 10 20 24; U14 5; U15 9; U17 4

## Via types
v1: diameter 0.635, hole 0.305, TOP to BOTTOM, 279 vias

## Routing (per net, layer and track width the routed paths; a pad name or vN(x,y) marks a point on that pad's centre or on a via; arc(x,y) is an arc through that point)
+2.5VA: length 70.3
  TOP w0.305: U13.7 121.61,9.64 121.75,9.78 122.13,9.78 122.26,9.65 U13.8 122.26,7.36
  TOP w0.381: 122.26,7.36 122.54,7.09 122.9,7.09 C39.2 v1(125.42,5.65) ; UNK+2.5VA.1 103.2,33.21 C5.2 105.22,33.15 U3.1 106.94,33.66 107.45,34.16 107.83,34.16 108.21,33.78 ; v1(109.6,9.88) U12.2 109.6,6.16 C32.2 110.18,4.06 C31.2 ; 108.21,33.78 U3.2 ; 108.21,33.78 108.21,33.81 108.56,34.16 109.1,34.16 109.48,33.78 U3.3
  TOP w0.508: U3.1 v1(106.94,31.32)
  BOTTOM w0.635: v1(125.42,5.65) 125.42,8.42 121.01,12.83 118.22,12.83 117.38,13.66 ; 117.38,13.66 113.6,9.88 v1(109.6,9.88) ; 117.38,13.66 117.38,15.27 106.94,25.71 v1(106.94,31.32)
+3.3VIO: length 87.4
  TOP w0.305: U15.1 147.02,21.2 C48.2 ; 148.23,16.27 U8.8 148.63,15.24 ; 154.95,43.82 P7.116 ; U11.5 132.53,55.49 C26.2 ; U8.3 149.93,12.7
  TOP w0.381: v1(146.82,10.67) R14.2 ; 148.23,16.27 147.64,15.68 C24.2 v1(147.07,16.64) ; 148.63,15.24 148.63,14.94 149.93,13.64 149.93,12.7 ; 154.95,43.82 151.65,43.82 v1(151.64,43.82) ; v1(149.99,19.02) C44.2 C48.2
  TOP w0.508: v1(151.64,52.25) 137.76,52.25 R35.2 134.58,55.43 C26.2
  BOTTOM w0.381: v1(146.82,10.67) 147.07,10.92 v1(147.07,16.64) 147.07,17.73 148.37,19.02 ; 148.37,19.02 146.82,20.57 146.82,29.46 151.64,34.29 v1(151.64,43.82) v1(151.64,52.25) ; 148.37,19.02 v1(149.99,19.02)
+3.3VISO: length 40.2
  TOP w0.305: U15.20 138.17,21.2 136.97,20 C50.2 ; 122.91,15.75 U13.16
  TOP w0.381: R20.2 135.95,18.66 v1(135.51,19.1) C49.2 C50.2 ; C1.2 131.74,8.61 R37.2 135.49,8.61 U1.2 136.27,8.64 136.53,8.89 136.53,9.65 136.27,9.91 U1.1 135.51,13.71 UNK+3.3VISO.1
  TOP w0.508: v1(126.8,17.2) C38.2 C37.2 122.91,16.03 122.91,15.75
  BOTTOM w0.635: 134.57,17.2 v1(126.8,17.2) ; 134.57,17.2 135.44,16.33 UNK+3.3VISO.1 ; 134.57,17.2 135.51,18.14 v1(135.51,19.1)
+5V_USB: length 36
  TOP w0.305: U9.5 145.48,56.31 145.48,55.79 ; 160.25,43.82 P7.5
  TOP w0.381: U10.5 139.06,55.81 138.88,55.63 C25.2
  TOP w0.508: 160.25,43.82 159.7,44.37 159.7,46.25 152.69,53.26 145.96,53.26 145.48,53.74 C23.2 ; C23.2 145.48,55.79 ; C23.2 144.36,54.74 143.19,53.57 139.32,53.57 138.88,54.01 C25.2 138.85,54.84 DS2.A
+5VA: length 130.8
  TOP w0.305: C45.1 116.53,24.96 v1(116.08,24.51) 116.08,23.88 116.39,23.57 U14.4 ; P6.10 v1(37.72,32.36)
  TOP w0.381: U2.1 111.61,46.1 111.26,46.45 111.26,46.99 111.64,47.37 U2.2 ; DS1.A 126.62,29.71 126.11,29.2 118.99,29.2 v1(118.68,29.51) 114.68,33.51 UNK+5VA.1 114.68,40.76 114.68,42.98 C10.2 114.3,43.36 R1.2 113.43,44.97 v1(112.77,44.31)
  TOP w0.508: R27.1 111.7,42.96 C6.2 ; C6.2 111.7,44.95 112.14,45.4 U2.1 ; C6.2 v1(112.77,44.31)
  BOTTOM w0.381: v1(116.08,24.51) 116.08,26.92 v1(118.68,29.51)
  BOTTOM w0.889: v1(37.72,32.36) 43.79,38.43 100.92,38.43 106.8,44.31 v1(112.77,44.31)
+VIN_PROTECTED: length 108.8
  TOP w0.305: v1(136.78,41.66) 137.29,42.16 U17.3
  TOP w0.381: C2.2 140.85,12.05 U1.8 ; U1.8 140.44,9.91 140.06,9.53 140.06,9.02 140.44,8.64 U1.7 141.74,8.64 142.12,8.25 142.12,6.48 141.74,6.1 U1.5 ; U1.8 v1(142.62,9.91)
  TOP w0.508: E1.1 v1(102.17,53.15)
  TOP w0.635: Q1.2 v1(97.8,58.05)
  BOTTOM w0.381: v1(142.62,9.91) 141.74,10.79 141.74,36.7 142.88,37.85 142.88,43.05 v1(142.24,43.69) 140.21,41.66 v1(136.78,41.66)
  BOTTOM w0.635: v1(142.24,43.69) 142.24,47.24 141.05,48.44 132.13,48.44 127.41,53.16 102.19,53.16 v1(102.17,53.15) 97.8,57.52 v1(97.8,58.05)
-2.5VA: length 61.4
  TOP w0.305: 118.36,9.66 U13.2 118.36,7.49 ; U14.3 117.79,22.92 v1(118.37,23.5) ; 120.96,7.38 U13.6 120.96,10.74 v1(120.02,11.68)
  TOP w0.381: v1(121.26,1.14) 121.35,1.23 C43.2 121.29,2.23 C29.1 119.65,4.25 C28.1 119.64,2.22 C30.1 v1(119.57,1.19) ; C35.2 116.02,5.59 C36.2 117.62,7.19 118.06,7.19 118.36,7.49 ; C31.1 111.57,4.06 C32.1 112.14,6.16 U12.4 112.14,9.24 113.12,10.22 C33.2 C34.2 v1(117.22,10.22) 117.8,10.22 118.36,9.66 ; C42.2 120.96,7.38
  TOP w0.508: v1(125.98,34.53) C14.2 122.72,34.53 U5.5 122.36,32.98 R8.2 122.11,32.72 C15.2 122.36,30.98 UNK-2.5VA.1
  BOTTOM w0.508: REF-.1 127.38,4.95 126.75,4.32 124.9,4.32 124.16,5.05 124.16,7.54 v1(120.02,11.68)
-5.8V_RAW: length 16.4
  TOP w0.254: R7.1 v1(135.89,46.99)
  TOP w0.305: C55.1 134.37,41.41 v1(134.43,41.47) C51.1 ; U17.7 139.69,42.16 U17.PAD 138.69,43.16 U17.12 138.69,45.39 C54.1 v1(138.24,46.8) ; R44.1 v1(137.31,37.74)
  TOP w0.381: L5.1 129.54,47.43 R46.1 v1(132.72,47.12)
  vias: v1(141.61,40.28) v1(141.61,39.27)
-5VA: length 123
  TOP w0.305: 37.27,30.33 35.87,30.33 P6.2 ; C46.1 110.37,22.27 U14.7 113.49,22.27 v1(113.92,21.84)
  TOP w0.381: UNK-5VA.1 125.86,45.33 C13.2 ; v1(121.92,40.99) 121.92,41.97 C7.2 122.02,42.07 R6.2 121.98,43.84 U4.5 123.27,45.95 123.89,45.33 C13.2 ; C13.2 124.08,42.01 R31.1
  TOP w0.635: 37.27,30.33 38.07,30.33 v1(38.1,30.36)
  BOTTOM w0.508: 113.92,30.99 v1(113.92,21.84)
  BOTTOM w0.635: v1(121.92,40.99) 121.92,38.99 113.92,30.99
  BOTTOM w0.889: 113.92,30.99 111.76,33.15 105.14,33.15 101.89,36.4 44.14,36.4 v1(38.1,30.36)
AGND: length 87.2
  TOP w0.203: v1(122.81,47.12) 122.64,47.12 121.98,47.77
  TOP w0.254: U4.1 121.98,47.73 121.37,47.12 119.38,47.12 119.15,47.35 R12.1
  TOP w0.305: v1(117.46,36.3) R13.1 118.85,36.07 121.88,36.07 122.36,36.55 U5.1 ; U15.19 137.36,21.85 C50.1 C49.1 134.71,21.4 v1(134.5,21.18) ; U15.11 137.79,27.05 v1(137.42,26.67) 137.69,26.4 U15.12 ; v1(122.94,12.83) 122.26,13.51 U13.17
  TOP w0.381: C11.1 121.98,50.04 U4.1 ; v1(128.23,31.56) Q2.2 137.54,33.13 R32.1 ; U2.4 114.21,49.91 R4.1 ; C13.1 122.82,47.13 v1(122.81,47.12) ; v1(143.83,31.5) C18.2 v1(142.75,30.35) ; C12.1 122.36,38.98 U5.1 ; C27.1 v1(123.45,49.4) ; C5.1 v1(105.16,35.56) 104.78,35.94 C4.1 ; C16.1 v1(116.32,48.12) ; R45.2 v1(134.24,46.99) ; D4.C v1(117.61,51.44)
  TOP w0.508: C2.1 v1(137.8,12.06) ; v1(122.69,3.35) C42.1 C39.1 v1(124.34,3.35) ; C17.1 v1(115.4,38.35) ; C8.1 v1(112.78,35.05) ; U1.4 v1(135.51,5.25) ; C45.2 v1(115.13,24.57) ; C40.1 C41.1 v1(120.78,19.55) ; R2.1 v1(99.67,64.11) ; R34.1 v1(134.58,3.96) ; v1(126.8,18.6) C38.1 C37.1 v1(124.08,19.51) ; v1(108.97,41.4) 108.46,40.89 C3.1 ; R4.1 v1(114.3,51.02) ; R29.1 v1(114.58,15.34) ; C6.1 v1(110.3,43.35) ; v1(110.36,24.63) C46.2 ; v1(123.78,2.16) C43.1 ; U3.4 v1(110.75,31.5) ; C14.1 v1(124.46,37.59)
  TOP w0.762: C1.1 v1(131.58,5.72) ; D1.1 106.06,64.36 J1.2 v1(106.31,61.98) ; D1.1 v1(102.87,62.87) ; D1.1 v1(102.87,65.91)
  vias: v1(7.62,21.59) v1(11.39,24.12) v1(11.39,19.04) v1(11.39,13.96) v1(11.43,54.61) v1(11.43,49.53) v1(11.43,44.45) v1(12.7,3.81) v1(13.97,66.04) v1(16.51,57.15) v1(16.51,52.07) v1(16.51,46.99) v1(16.51,41.91) v1(16.47,21.58) v1(16.47,16.5) v1(16.47,11.42) v1(17.78,3.81) v1(19.05,66.04) v1(21.59,49.53) v1(21.59,44.45) v1(21.59,39.37) v1(21.59,34.29) v1(21.59,29.21) v1(21.55,24.12) v1(21.55,19.04) v1(21.55,13.96) v1(22.86,3.81) v1(24.13,66.04) v1(26.67,46.99) v1(26.67,41.91) v1(26.67,36.83) v1(26.67,31.75) v1(26.67,26.67) v1(26.63,21.58) v1(26.63,16.5) v1(26.63,11.42) v1(27.94,3.81) v1(29.21,66.04) v1(31.75,24.13) v1(31.75,19.05) v1(33.02,3.81) v1(34.29,66.04) v1(34.29,57.15) v1(38.1,21.59) v1(38.1,16.51) v1(38.1,3.81) v1(39.37,66.04) v1(39.37,54.61) v1(39.37,49.53) v1(39.37,44.45) v1(43.18,24.13) v1(43.18,19.05) v1(43.18,13.97) v1(43.18,3.81) v1(44.45,66.04) v1(44.45,57.15) v1(44.45,52.07) v1(48.26,21.59) v1(48.26,16.51) v1(48.26,11.43) v1(48.26,3.81) v1(49.53,66.04) v1(49.53,54.61) v1(49.53,49.53) v1(49.53,44.45) v1(50.8,31.75) v1(53.3,24.12) v1(53.3,19.04) v1(53.3,13.96) v1(53.34,3.81) v1(54.61,66.04) v1(54.61,57.15) v1(54.61,52.07) v1(54.61,46.99) v1(54.61,41.91) v1(55.88,31.75) v1(58.38,21.58) v1(58.38,16.5) v1(58.38,11.42) v1(58.42,3.81) v1(59.69,66.04) v1(59.69,54.61) v1(59.69,49.53) v1(59.69,41.91) v1(60.96,31.75) v1(63.46,24.12) v1(63.46,19.04) v1(63.46,13.96) v1(63.5,3.81) v1(64.77,66.04) v1(64.77,57.15) v1(64.77,52.07) v1(64.77,46.99) v1(64.77,41.91) v1(66.04,31.75) v1(68.54,21.58) v1(68.54,16.5) v1(68.54,11.42) v1(68.58,3.81) v1(69.85,66.04) v1(69.85,54.61) v1(69.85,49.53) v1(69.85,44.45) v1(73.62,24.12) v1(73.62,19.04) v1(73.62,13.96) v1(74.93,57.15) v1(74.93,52.07) v1(74.93,46.99) v1(74.93,41.91) v1(74.93,31.75) v1(78.7,21.58) v1(78.7,16.5) v1(78.7,11.42) v1(78.74,49.53) v1(80.01,31.75) v1(81.28,3.81) v1(82.55,66.04) v1(83.78,24.12) v1(83.78,19.04) v1(83.78,13.96) v1(83.82,52.07) v1(83.82,46.99) v1(85.09,31.75) v1(86.36,3.81) v1(87.63,66.04) v1(91.44,3.81) v1(92.71,66.04) v1(101.6,15.24) v1(101.6,8.89) v1(101.6,3.81) v1(108.08,36.58) v1(108.08,35.05) v1(108.7,48.77) v1(108.7,47.24) v1(108.84,35.81) v1(109.48,48.01) v1(109.6,36.58) v1(109.6,35.05) v1(110.23,48.77) v1(110.23,47.24) v1(137.42,8.76) v1(137.42,7.24) v1(138.18,8) v1(138.94,8.76) v1(138.94,7.24) v1(147.32,46.48) v1(147.32,45.59) v1(147.32,44.7)
AGND2: length 70.3
  TOP w0.305: U15.10 147.32,27.05 v1(147.96,27.69) ; C26.1 132.1,56.34 129.88,56.34 129.65,56.56 U11.3 v1(128.66,57.27) ; U15.2 147.77,21.85 C48.1 C44.1 v1(151.01,21.4) ; U8.7 v1(149.28,17.58) ; U8.4 150.58,12.53 v1(151.01,12.95)
  TOP w0.356: P7.98 v1(157.86,33.02) ; v1(157.86,19.28) 157.81,19.22 P7.75 ; P7.3 v1(160.61,45.02) ; P7.36 160.64,25.22 v1(160.53,25.12) ; P7.118 v1(154.88,45.02) ; P7.23 v1(160.54,33.02) ; P7.104 v1(157.82,36.62) ; P7.109 v1(157.86,39.62) ; P7.6 160.58,43.22 v1(160.28,42.93) ; P7.28 v1(160.58,30.02) ; P7.4 v1(163.45,44.42) ; P7.52 v1(160.53,15.62) ; P7.93 v1(157.74,30.02) ; P7.17 v1(160.58,36.62) ; P7.81 v1(157.7,22.82) ; P7.86 v1(157.86,25.82) ; P7.11 v1(160.62,40.22) ; P7.63 v1(157.7,12.02) ; P7.40 v1(160.57,22.82) ; P7.58 v1(160.57,12.02) ; P7.69 v1(157.73,15.62) ; P7.117 v1(157.76,44.42) ; P7.115 v1(157.82,43.22) ; P7.46 v1(160.61,19.22)
  TOP w0.381: C23.1 146.39,55.23 146.39,57.33 146.73,57.67 U9.3 148.1,57.67 v1(148.34,57.91) ; U10.3 v1(140.84,58.8) ; J2.4 142.91,60.62 D2.A ; D3.A 127.92,60.62 J3.4 ; v1(141.23,54.86) C25.1 ; v1(145.23,31.5) C18.1 v1(146.18,30.35) ; R15.1 v1(151.39,9.78)
  TOP w0.508: R16.1 v1(151.37,8.13) ; C24.1 v1(146.05,14.29)
CS: length 11.9
  TOP w0.203: R22.1 137.71,24.45 U15.15 140.78,24.45 141.33,23.9 R20.1
DIN: length 4
  TOP w0.203: U15.17 137.36,23.15 R24.1
DOUT: length 22.2
  TOP w0.203: R25.2 128.12,13.43 132.08,17.4 139.96,17.4 140.59,18.03 140.59,23.49 140.29,23.8 U15.16
EN_ADCOFFSETCAL: length 12.9
  TOP w0.203: v1(120.4,16) 120.96,15.44 U13.19 ; U14.6 113.99,22.92 v1(115.07,21.84)
  BOTTOM w0.203: v1(115.07,21.84) 115.07,21.34 v1(120.4,16)
GP_LED_ON: length 53.5
  TOP w0.203: v1(158.37,20.07) 157.64,20.07 157.39,19.82 P7.76 ; U10.2 v1(142.11,57.01)
  BOTTOM w0.203: v1(142.11,57.01) 150.38,57.01 153.17,54.23 153.17,24 155.2,21.97 157.86,21.97 158.37,21.46 v1(158.37,20.07)
LED_ONI: length 11.7
  TOP w0.203: U15.13 140.18,25.75 140.59,26.16 140.59,32.36 139.69,33.26 R32.2 138.81,33.19 Q2.1
SCLK: length 3.6
  TOP w0.305: 137.8,22.5 U15.18
  TOP w0.381: 137.8,22.5 136.36,22.5 R23.1
SPI_MISO_SDP: length 23.1
  TOP w0.203: P7.74 158.58,18.62 159.01,19.05 159.01,22.73 v1(157.72,24.02) P7.83 154.46,24.02 154.31,23.88 150.92,23.88 150.75,24.04 150.75,25.55 R39.1 ; P7.35 v1(159.56,25.82)
  BOTTOM w0.203: v1(159.56,25.82) 157.76,24.02 v1(157.72,24.02)
START_TRIGGER_OUT: length 2.4
  TOP w0.203: R33.1 U9.2
SYNCI: length 5.1
  TOP w0.203: U15.14 137.76,25.1 136.63,26.22 136.63,27.17 R26.2
TRIGGER_INPUT: length 51.8
  TOP w0.305: 160.84,21.02 P7.43
  TOP w0.381: R10.2 136.3,51.92 136.93,51.28 153.19,51.28 158.75,45.72 158.75,24.13 159.77,23.11 159.77,22.1 160.84,21.02
UNNAMED_3_ADP2442_I8_BST: length 5.6
  TOP w0.305: C57.2 141.48,47.75 140.85,47.12 140.85,45.34 140.47,44.96 139.96,44.96 139.69,44.69 U17.10
UNNAMED_3_ADP2442_I8_COMP: length 4.2
  TOP w0.305: R43.2 135.89,42.47 C51.2 135.95,42.66 U17.2
UNNAMED_3_ADP2442_I8_FB: length 3.8
  TOP w0.254: U17.1 136.95,43.16 R7.2 R45.1
UNNAMED_3_ADP2442_I8_FREQ: length 2.2
  TOP w0.305: U17.5 139.19,39.97 R44.2
UNNAMED_3_ADP2442_I8_SW: length 9.9
  TOP w0.279: 142.88,41.71 141.93,42.66 U17.8 ; L4.1 144.01,41.85 144.01,47.7 C57.1
  TOP w0.305: 142.88,41.71 L4.1
UNNAMED_3_ADP2442_I8_SYNC: length 16.2
  TOP w0.305: U17.6 140.3,40.49 v1(140.34,40.49) ; v1(139.64,46.8) C54.2 139.19,45.39 U17.11
  BOTTOM w0.254: v1(139.64,46.8) 135.59,42.76 135.59,40.99 136.2,40.39 140.24,40.39 v1(140.34,40.49)
UNNAMED_3_ADP7118V3_I3_EN: length 13.1
  TOP w0.381: U3.5 R27.2 109.38,40.54 108.21,39.37 U3.7 108.21,37.85 107.83,37.47 107.32,37.47 107.06,37.72 107.06,38.35 U3.8 106.8,38.62 C4.2 ; R28.2 104.78,38.62
  TOP w0.508: 104.78,38.62 C4.2
UNNAMED_3_ADP7118V3_I3_SS: length 4.4
  TOP w0.254: C8.2 112.06,37.34 110.11,37.34 109.48,37.97 U3.6
UNNAMED_3_ADP7118V3_I4_EN: length 21.7
  TOP w0.381: 104.78,43.69 104.78,43.69 C3.2 106.81,43.94 U2.8 105.82,46.1 105.54,46.38 105.54,47.12 105.79,47.37 105.79,47.37 ; 104.78,43.69 R28.1 ; 104.78,43.69 103.64,44.83 E1.2 ; 105.79,47.37 105.54,47.62 105.54,49.66 105.79,49.91 U2.5 ; 105.79,47.37 U2.7
UNNAMED_3_ADP7118V3_I4_SENSE: length 5.9
  TOP w0.254: U2.3 114.19,48.64 R4.2 R1.1 R3.1
UNNAMED_3_ADP7118V3_I5_SENSE: length 3.8
  TOP w0.381: R34.2 R37.1 133.71,7.37 U1.3
UNNAMED_3_ADP7182_I6_ADJ: length 6.2
  TOP w0.203: U4.4 120.01,45.87 R12.2 118.24,44.03 R9.1 120.4,43.65 R6.1
UNNAMED_3_ADP7182_I6_EN: length 32.2
  TOP w0.305: U4.2 121.03,49.59 C11.2 120.08,49.53 U4.3
  TOP w0.381: C27.2 L5.2 128.27,47.43 R46.2 ; C27.2 126.51,50.79 125.43,51.87 121.2,51.87 D4.A 121.11,51.08 121.11,50.56 C11.2 120.06,50.57 119.29,50.57 C16.2 ; C27.2 v1(126.51,47.89) ; R30.1 v1(125.7,39.85)
  BOTTOM w0.381: v1(126.51,47.89) 125.05,46.43 125.05,40.51 v1(125.7,39.85)
UNNAMED_3_ADP7182_I7_ADJ: length 6
  TOP w0.381: U5.4 118.69,34.89 R13.2 R11.1 120.65,32.74 R8.1
UNNAMED_3_ADP7182_I7_EN: length 12.1
  TOP w0.381: C12.2 120.46,38.48 U5.3 ; C12.2 122.51,40.53 R31.2 124.08,39.01 R30.2 ; C12.2 121.42,38.54 121.42,37.23 U5.2
  TOP w0.508: C17.2 118.51,38.37 119.13,38.99 C12.2
UNNAMED_3_CAP_I33_N1: length 1.8
  TOP w0.254: R3.2 115.95,44.19 115.76,44 C10.1
UNNAMED_3_CAP_I56_N1: length 2.1
  TOP w0.381: R11.2 118.66,31.23 C15.1
UNNAMED_3_CAP_I57_N1: length 2
  TOP w0.203: R9.2 118.77,42.03 C7.1
UNNAMED_3_CAP_I91_N2: length 1.5
  TOP w0.305: C55.2 134.41,38.76 R43.1
UNNAMED_3_CN4PV6_I1_N1: length 9.4
  TOP w1.016: J1.1B J1.1A 117.72,57.92 F1.1
UNNAMED_3_DIOLED_I44_N: length 1.9
  TOP w0.381: R5.2 134.26,29.71 DS1.C
UNNAMED_3_DIOV3_I120_N2: length 25.7
  TOP w0.635: Q1.3 102.85,60.32 D1.2
  TOP w1.016: D1.2 102.87,56.26 104.04,55.1 F1.2
UNNAMED_3_RES_I16_N2: length 2
  TOP w0.254: R2.2 97.8,62.72 Q1.1
UNNAMED_3_RES_I43_N1: length 2.5
  TOP w0.381: Q2.3 138.12,29.72 R5.1
UNNAMED_4_AD71722_I1_AIN0: length 15
  TOP w0.203: RN1.7 116.1,17.06 116.29,16.87 116.8,16.87 117,17.07 RN1.8 117.21,17.89 118.75,17.89 ; AIN0.1 119.76,20.19 119.76,18.91 118.75,17.89 ; U13.21 119.66,15.83 118.75,16.74 C47.2 118.75,17.89
UNNAMED_4_AD71722_I1_AIN1: length 9.9
  TOP w0.203: 115.09,16.81 115.81,16.1 118.47,16.1 119.01,15.57 U13.22 ; 115.09,16.81 114.59,16.81 114.4,17.01 RN1.5 113.52,17.68 113.36,17.83 C9.2 ; 115.09,16.81 115.3,17.02 RN1.6
UNNAMED_4_AD71722_I1_AIN2: length 110.6
  TOP w0.203: C47.1 118.53,19.02 117.96,19.02 117.48,18.54 116.29,18.54 116.1,18.73 RN1.2 116.1,20 115.91,20.19 115.32,20.19 ; U13.23 118.36,13.37 118.19,13.21 116.29,13.21 116.06,13.44 R29.2 116.06,15.22 114.92,16.36 114.03,16.36 113.47,16.92 111.83,16.92 111.37,17.37 111.37,19.04 ; 115.32,20.19 115.3,20.17 RN1.3 ; 115.32,20.19 114.58,20.19 114.4,20 RN1.4 113.75,19.38 113.6,19.23 C9.1 ; C9.1 112.52,19.68 113.29,20.45 113.29,21.46 113.13,21.62 U14.8 ; C9.1 111.56,19.23 111.37,19.04 ; SGND.1 111.37,19.04
  TOP w0.305: P6.8 36.8,31.86 36.96,31.7 36.96,31.36 ; P6.6 36.96,31.36 ; 36.96,31.36 36.96,31.04 36.78,30.86 P6.4
  TOP w0.381: 36.96,31.36 39.76,31.36 v1(40.64,30.48)
  BOTTOM w0.889: v1(40.64,30.48) 43.13,27.99 100.02,27.99 SGND.1
UNNAMED_4_AD71722_I1_CSN: length 17.6
  TOP w0.203: U13.14 124.21,15.37 124.82,15.98 127.36,15.98 131.96,20.57 131.96,24.1 R22.2
UNNAMED_4_AD71722_I1_DIN: length 20.6
  TOP w0.203: R24.2 135,24.03 135,22.58 133.73,21.31 133.73,19.81 127.38,13.46 127.38,12.1 124.86,9.58 U13.12
UNNAMED_4_AD71722_I1_DOUT: length 5.1
  TOP w0.203: U13.11 124.21,10.26 R25.1
UNNAMED_4_AD71722_I1_REF: length 36.9
  TOP w0.305: C36.1 119.01,7.18 U13.3 119.01,10.03
  TOP w0.381: C33.1 113.25,11.62 112.81,11.18 111.23,11.18 110.87,11.53 U12.6 ; C33.1 C34.1 117.41,11.62 119.01,10.03 ; C33.1 v1(114.3,12.57) ; C36.1 C35.1
  BOTTOM w0.203: REF+.1 103.63,15.49 105.29,17.14 114,17.14 115.48,15.67 115.48,13.75 v1(114.3,12.57)
UNNAMED_4_AD71722_I1_REFOUT: length 3
  TOP w0.305: U13.4 119.66,5.67 C28.2
UNNAMED_4_AD71722_I1_SCLK: length 13.6
  TOP w0.381: R23.2 132.72,21.56 132.72,20.57 126.62,14.47 U13.13
UNNAMED_4_AD71722_I1_SYNCN: length 19.5
  TOP w0.203: U13.15 123.56,15.48 124.54,16.46 127.08,16.46 131.32,20.7 131.32,25.12 R26.1
UNNAMED_4_ADG1419_I8_D: length 141.2
  TOP w0.203: U14.1 117,21.6 RN1.1
  TOP w0.254: P6.9 31.12,32.36 30.87,32.61 30.87,34.42 34.8,38.35 80.01,38.35 85.73,44.07 J4.1 ; U14.1 119.36,21.62 R36.2 120.03,21.61 120.53,22.1 120.53,24.75 VOUT.1 119.25,26.04 117.35,27.94 103,27.94 93.71,37.23 v1(93.71,55.88)
  BOTTOM w0.254: J4.1 v1(93.71,55.88)
UNNAMED_4_ADG1419_I8_SA: length 94.2
  TOP w0.203: R36.1 119.09,23.08 118.29,22.27 U14.2
  TOP w0.254: P6.5 v1(30.75,31.36)
  TOP w0.305: U14.2 115.91,22.27 111.51,26.67 v1(95.25,26.67)
  BOTTOM w0.254: v1(30.75,31.36) 33.41,31.36 38.1,26.67 v1(95.25,26.67)
UNNAMED_4_CAP_I35_N2: length 15.8
  TOP w0.305: C29.2 120.31,6.62 U13.5 120.31,10.05 v1(119.89,10.46)
  TOP w0.381: v1(117.22,2.16) C30.2
  BOTTOM w0.381: v1(117.22,2.16) 119.89,4.83 v1(119.89,10.46)
UNNAMED_4_CAP_I42_N2: length 4.8
  TOP w0.305: 121.61,15.82 121.6,15.82 120.78,16.64 C41.2 ; 121.61,15.82 U13.18 ; 121.61,15.82 122.43,16.63 C40.2
UNNAMED_5_741G04_I48_Y: length 3.4
  TOP w0.203: D2.C R17.2 145.54,59.28 U9.4
UNNAMED_5_741G04_I49_Y: length 1.8
  TOP w0.254: U10.4 139.06,58.91 R18.2
UNNAMED_5_741G14_I52_Y: length 7.1
  TOP w0.305: U11.4 129.65,54.63 130.03,54.25 133.95,54.25 R10.1
UNNAMED_5_ADUM3151_I16_MCLK: length 4
  TOP w0.33: 147.7,22.5 U15.3
  TOP w0.381: 147.7,22.5 149.52,22.5 R41.2
UNNAMED_5_ADUM3151_I16_MI: length 5.2
  TOP w0.203: U15.5 148.03,23.8 149.1,24.87 149.1,25.37 R39.2
UNNAMED_5_ADUM3151_I16_MO: length 4.5
  TOP w0.203: U15.4 148.52,23.15 R40.2
UNNAMED_5_ADUM3151_I16_MSSN: length 6.2
  TOP w0.203: U15.6 148.05,24.45 148.59,24.99 148.59,26.52 R38.2
UNNAMED_5_ADUM3151_I16_VIA: length 17.8
  TOP w0.203: P7.78 v1(157.74,21.02) ; U15.7 147.78,25.1 v1(147.96,25.27)
  BOTTOM w0.203: v1(147.96,25.27) 147.32,25.91 147.32,26.54 147.7,26.92 149.23,26.92 155.13,21.02 v1(157.74,21.02)
UNNAMED_5_ADUM3151_I16_VIB: length 12.8
  TOP w0.203: v1(147.96,26.29) 147.42,25.75 U15.8 ; P7.77 v1(154.71,20.42)
  BOTTOM w0.203: v1(147.96,26.29) 148.85,26.29 v1(154.71,20.42)
UNNAMED_5_CN120PV4_I1_EEPROMA0: length 29.3
  TOP w0.203: P7.56 160.67,13.22 154.56,7.11 146.31,7.11 145.8,7.62 145.8,12.06 146.43,12.7 148.34,12.7 148.63,12.4 U8.1 148.63,9.87 R15.2
UNNAMED_5_CN120PV4_I1_GPIO2: length 49.5
  TOP w0.305: P7.44 163.18,20.42
  TOP w0.381: R33.2 161.39,57.02 164.21,54.2 164.21,21.46 163.18,20.42
UNNAMED_5_CN120PV4_I1_SCL0: length 13.3
  TOP w0.203: U8.6 149.93,15.17 150.37,14.73 152.66,14.73 153.93,16 153.93,20.83 154.72,21.62 P7.79
UNNAMED_5_CN120PV4_I1_SDA0: length 12.4
  TOP w0.203: P7.80 154.31,22.22 153.23,21.15 153.23,16.32 152.07,15.16 150.83,15.16 150.58,15.41 U8.5
UNNAMED_5_CN120PV4_I1_SPICLK: length 5
  TOP w0.381: P7.82 154.87,23.42 154.44,22.99 R41.1
UNNAMED_5_CN120PV4_I1_SPIMOSI: length 4.8
  TOP w0.203: P7.84 156.3,24.64 R40.1
UNNAMED_5_CN120PV4_I1_SPISELA: length 5.9
  TOP w0.203: R38.1 154.2,25.22 P7.85
UNNAMED_5_CNBNC5P_I53_CNTR: length 5.5
  TOP w0.203: J2.1 147.07,59.33 R17.1
UNNAMED_5_CNBNC5P_I54_CNTR: length 5.5
  TOP w0.203: J3.1 132.08,59.33 R19.1
UNNAMED_5_DIOLED_I62_N: length 3
  TOP w0.254: R18.1 137.04,59.16 DS2.C
UNNAMED_5_IC24FC256_I3_A1: length 5.6
  TOP w0.203: U8.2 149.28,11.66 149.28,8.79 148.62,8.13 R16.2 146.84,8.13 R14.1
UNNAMED_5_RES_I26_N1: length 9.5
  TOP w0.203: 130.58,58.45 130.3,58.16 U11.2 ; 130.58,58.45 134.34,58.45 134.75,58.04 R35.1 ; 130.58,58.45 R19.2 D3.C
VGUARD: length 60.2
  TOP w0.305: 63,61.28 VGUARD.1 54.74,40.01 32.64,40.01 29.47,36.83 29.47,30.86 29.97,30.36 P6.1

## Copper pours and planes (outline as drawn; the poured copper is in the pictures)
